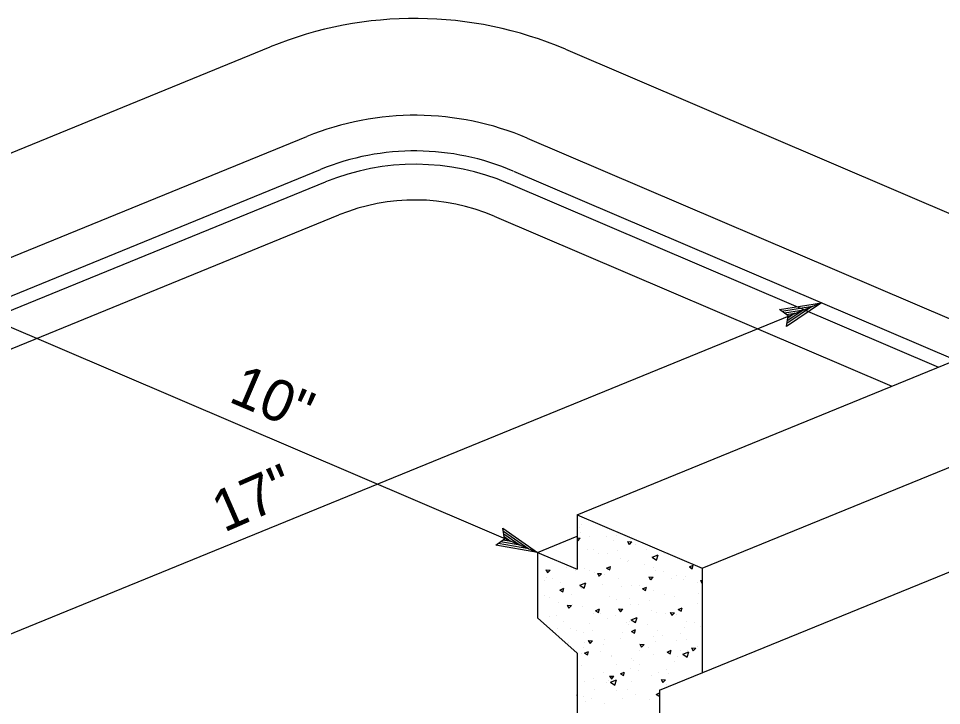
# Model space of a CAD drawing. Extents: x -123486 to -116575, y -107066 to -101122.
# Drawn here: x -117088.2 to -116954.3, y -101409.8 to -101310.1 of the extents above; entities that cross this region are included whole.
import ezdxf

# ---------------------------------------------------------------- set-up
doc = ezdxf.new("R2010")
doc.units = 0
for name, color, linetype in [('G-MARK', 7, 'Continuous'), ('G-TEXT', 7, 'Continuous'), ('Misc CnstDet(22)', 7, 'Continuous')]:
    doc.layers.add(name, color=color, linetype=linetype)

msp = doc.modelspace()

# ---------------------------------------------------------------- linework, layer by layer
at = {"layer": 'G-MARK'}
for p, q in [((-116971.72, -101351.36), (-117114.25, -101409.62)), ((-117094.77, -101352.6), (-117012.91, -101387.59))]:
    msp.add_line(p, q, dxfattribs=at)
at = {"layer": 'G-TEXT'}
for p, q in [((-116977.79, -101352.32), (-116971.72, -101351.36)), ((-116976.55, -101353.27), (-116977.79, -101352.32)), ((-116977.79, -101352.32), (-116977.79, -101352.32)), ((-116977.45, -101352.57), (-116973, -101351.86)), ((-116977.1, -101352.82), (-116974.28, -101352.37)), ((-116971.72, -101351.36), (-116976.8, -101354.8)), ((-116973.01, -101351.87), (-116976.72, -101354.38)), ((-116974.28, -101352.37), (-116976.68, -101354)), ((-116971.72, -101351.36), (-116971.72, -101351.36)), ((-116976.81, -101353.08), (-116975.57, -101352.88)), ((-116976.8, -101354.8), (-116976.55, -101353.27)), ((-116975.57, -101352.88), (-116976.59, -101353.57)), ((-116976.8, -101354.8), (-116976.8, -101354.8)), ((-117017.72, -101385.62), (-117017.95, -101384.07)), ((-117017.95, -101384.07), (-117017.95, -101384.07)), ((-117017.95, -101384.07), (-117012.91, -101387.59)), ((-117017.88, -101384.49), (-117014.18, -101387.07)), ((-117018.96, -101386.54), (-117017.72, -101385.62)), ((-117015.46, -101386.54), (-117018.31, -101386.05)), ((-117016.74, -101386.02), (-117017.96, -101385.8)), ((-117017.8, -101384.91), (-117015.46, -101386.54)), ((-117017.77, -101385.29), (-117016.74, -101386.02)), ((-117012.91, -101387.59), (-117018.96, -101386.54)), ((-117018.96, -101386.54), (-117018.96, -101386.54)), ((-117014.19, -101387.07), (-117018.61, -101386.3)), ((-117012.91, -101387.59), (-117012.91, -101387.59))]:
    msp.add_line(p, q, dxfattribs=at)
at = {"layer": 'Misc CnstDet(22)'}
for p, q in [((-117181.69, -101367.35), (-117051.7, -101314.22)), ((-117008.88, -101314.56), (-116938.85, -101344.49)), ((-117168.96, -101377.33), (-117046.39, -101327.22)), ((-117014.4, -101327.48), (-116952.83, -101353.79)), ((-117168.08, -101382.57), (-117044.43, -101332.02)), ((-117016.43, -101332.24), (-116952.31, -101359.65)), ((-117165.58, -101383.64), (-117043.69, -101333.81)), ((-117017.2, -101334.02), (-116954.75, -101360.71)), ((-117158.88, -101386.5), (-117041.73, -101338.61)), ((-117019.23, -101338.79), (-116961.49, -101363.47)), ((-117007.18, -101382.14), (-116952.87, -101359.94)), ((-116989.02, -101389.9), (-116939.05, -101369.47)), ((-117007.18, -101382.14), (-116989.02, -101389.9)), ((-117007.18, -101382.14), (-117007.18, -101390.04)), ((-116995.2, -101407.6), (-116933.16, -101382.24)), ((-117006.89, -101383.95), (-117006.89, -101383.95)), ((-117006.7, -101384.63), (-117006.7, -101384.63)), ((-117006.49, -101383.54), (-117006.49, -101383.54)), ((-117012.91, -101387.59), (-117007.18, -101385.25)), ((-117007.18, -101385.5), (-117006.71, -101385.53)), ((-117007.18, -101385.75), (-117007.08, -101385.92)), ((-117007.08, -101385.92), (-117006.71, -101385.53)), ((-117005.31, -101385.3), (-117005.31, -101385.3)), ((-117002.85, -101385.24), (-117002.85, -101385.24)), ((-117001.94, -101385.93), (-117001.94, -101385.93)), ((-117001.42, -101385.14), (-117001.42, -101385.14)), ((-116999.85, -101386.01), (-116999.6, -101386.44)), ((-116999.85, -101386.01), (-116999.23, -101386.05)), ((-116999.59, -101386.44), (-116999.23, -101386.06)), ((-116999.42, -101385.77), (-116999.42, -101385.77)), ((-117005.66, -101387.13), (-117005.66, -101387.13)), ((-117004.8, -101387.19), (-117004.8, -101387.19)), ((-117001.36, -101387.35), (-117001.36, -101387.35)), ((-116998.67, -101386.5), (-116998.67, -101386.5)), ((-116997.18, -101387.23), (-116997.18, -101387.23)), ((-117012.91, -101387.59), (-117007.18, -101390.04)), ((-117012.91, -101387.59), (-117012.91, -101397.07)), ((-117004.12, -101387.71), (-117004.12, -101387.71)), ((-117002.79, -101387.82), (-117002.79, -101387.82)), ((-117000.9, -101388.43), (-117000.9, -101388.43)), ((-116996.3, -101388.29), (-116995.43, -101387.95)), ((-116996.3, -101388.29), (-116995.68, -101388.7)), ((-116995.68, -101388.71), (-116995.43, -101387.95)), ((-116994.54, -101387.78), (-116994.54, -101387.78)), ((-116992.43, -101388.52), (-116992.43, -101388.52)), ((-117008.77, -101389.82), (-117008.77, -101389.82)), ((-117006.17, -101389.87), (-117006.17, -101389.87)), ((-117002.89, -101389.88), (-117002.32, -101389.62)), ((-117002.89, -101389.88), (-117002.45, -101390.13)), ((-117002.45, -101390.13), (-117002.32, -101389.62)), ((-116999.93, -101388.98), (-116999.93, -101388.98)), ((-116999.76, -101388.78), (-116999.76, -101388.78)), ((-116997.41, -101389.4), (-116997.41, -101389.4)), ((-116996.15, -101389.73), (-116996.15, -101389.73)), ((-116990.89, -101389.71), (-116990.33, -101389.45)), ((-116990.89, -101389.71), (-116990.46, -101389.96)), ((-116990.46, -101389.97), (-116990.32, -101389.45)), ((-116989.04, -101390.07), (-116989.04, -101390.07)), ((-116989.02, -101389.9), (-116989.02, -101405.08)), ((-117011.73, -101390.11), (-117011.47, -101390.53)), ((-117011.73, -101390.11), (-117011.1, -101390.15)), ((-117011.55, -101391.29), (-117011.55, -101391.29)), ((-117011.47, -101390.54), (-117011.1, -101390.15)), ((-117010.69, -101391.36), (-117010.69, -101391.36)), ((-117007.46, -101390.23), (-117007.46, -101390.23)), ((-117005.38, -101390.18), (-117005.38, -101390.18)), ((-117004.63, -101390.52), (-117004.63, -101390.52)), ((-117004.24, -101390.63), (-117003.99, -101391.06)), ((-117004.24, -101390.63), (-117003.62, -101390.67)), ((-117004.01, -101391.12), (-117004.01, -101391.12)), ((-117003.99, -101391.06), (-117003.62, -101390.68)), ((-117003.13, -101390.83), (-117003.13, -101390.83)), ((-116996.76, -101391.15), (-116996.51, -101391.58)), ((-116996.76, -101391.15), (-116996.14, -101391.2)), ((-116996.5, -101391.58), (-116996.14, -101391.2)), ((-116995.8, -101390.25), (-116995.8, -101390.25)), ((-116994.69, -101390.37), (-116994.69, -101390.37)), ((-116992.69, -101391.01), (-116992.69, -101391.01)), ((-116991.39, -101391.03), (-116991.39, -101391.03)), ((-117011.88, -101391.61), (-117011.88, -101391.61)), ((-117009.55, -101391.93), (-117009.55, -101391.93)), ((-117006.79, -101392.35), (-117005.92, -101392.01)), ((-117006.79, -101392.35), (-117006.17, -101392.77)), ((-117006.65, -101392.66), (-117006.65, -101392.66)), ((-117006.17, -101392.77), (-117005.92, -101392.02)), ((-117003.51, -101392.28), (-117003.51, -101392.28)), ((-117001.19, -101391.45), (-117001.19, -101391.45)), ((-117000.68, -101392.57), (-117000.68, -101392.57)), ((-116999.25, -101392.42), (-116999.25, -101392.42)), ((-116998.07, -101392.43), (-116998.07, -101392.43)), ((-116997.69, -101392.88), (-116997.12, -101392.62)), ((-116997.26, -101393.13), (-116997.12, -101392.62)), ((-116997.07, -101392.72), (-116997.07, -101392.72)), ((-116993.46, -101391.45), (-116993.46, -101391.45)), ((-116991.76, -101391.55), (-116991.76, -101391.55)), ((-116989.65, -101391.96), (-116989.65, -101391.96)), ((-116989.28, -101391.68), (-116989.02, -101392.1)), ((-116989.28, -101391.68), (-116989.02, -101391.69)), ((-116989.02, -101392.11), (-116989.02, -101392.11)), ((-117011.95, -101393.83), (-117011.95, -101393.83)), ((-117009.68, -101393.05), (-117009.12, -101392.79)), ((-117009.68, -101393.05), (-117009.25, -101393.3)), ((-117009.25, -101393.3), (-117009.12, -101392.79)), ((-117007.92, -101393.66), (-117007.92, -101393.66)), ((-117006.51, -101392.88), (-117006.51, -101392.88)), ((-117002.46, -101393.92), (-117002.46, -101393.92)), ((-116997.69, -101392.88), (-116997.26, -101393.13)), ((-116996.06, -101393.06), (-116996.06, -101393.06)), ((-116994.49, -101393.72), (-116994.49, -101393.72)), ((-116993.03, -101394.02), (-116993.03, -101394.02)), ((-116993.03, -101394.02), (-116993.03, -101394.02)), ((-116989.5, -101393.5), (-116989.5, -101393.5)), ((-117011.18, -101394.18), (-117011.18, -101394.18)), ((-117009.89, -101394.93), (-117009.89, -101394.93)), ((-117008.64, -101395.25), (-117008.38, -101395.68)), ((-117008.64, -101395.25), (-117008.01, -101395.29)), ((-117008.38, -101395.68), (-117008.01, -101395.3)), ((-117007.91, -101395.13), (-117007.91, -101395.13)), ((-117001.45, -101394.48), (-117001.45, -101394.48)), ((-116999.56, -101394.33), (-116999.56, -101394.33)), ((-116999.44, -101395.11), (-116999.44, -101395.11)), ((-116998.33, -101395.19), (-116998.33, -101395.19)), ((-116996.73, -101394.62), (-116996.73, -101394.62)), ((-116989.74, -101395.01), (-116989.74, -101395.01)), ((-117010.14, -101396.69), (-117010.14, -101396.69)), ((-117006.42, -101395.48), (-117006.42, -101395.48)), ((-117004.82, -101396.53), (-117004.82, -101396.53)), ((-117004.49, -101396.05), (-117003.92, -101395.79)), ((-117004.49, -101396.05), (-117004.05, -101396.3)), ((-117004.05, -101396.3), (-117003.92, -101395.79)), ((-117003.97, -101395.71), (-117003.97, -101395.71)), ((-117003.72, -101396.39), (-117003.72, -101396.39)), ((-117001.66, -101396.78), (-117001.66, -101396.78)), ((-117001.15, -101395.77), (-117000.9, -101396.2)), ((-117001.15, -101395.77), (-117000.53, -101395.82)), ((-117000.9, -101396.2), (-117000.53, -101395.82)), ((-116996.4, -101396.07), (-116996.4, -101396.07)), ((-116995.61, -101396.38), (-116995.61, -101396.38)), ((-116994.29, -101396.49), (-116994.29, -101396.49)), ((-116993.67, -101396.3), (-116993.41, -101396.72)), ((-116993.67, -101396.3), (-116993.05, -101396.34)), ((-116993.41, -101396.73), (-116993.05, -101396.34)), ((-116992.77, -101396.67), (-116992.77, -101396.67)), ((-116992.49, -101395.88), (-116991.93, -101395.62)), ((-116992.49, -101395.88), (-116992.06, -101396.13)), ((-116992.06, -101396.13), (-116991.93, -101395.62)), ((-117007.18, -101402.21), (-117012.91, -101397.07)), ((-117011.19, -101396.83), (-117011.19, -101396.83)), ((-117009.17, -101397.6), (-117009.17, -101397.6)), ((-117005.39, -101397.98), (-117005.39, -101397.98)), ((-117002.82, -101397.16), (-117002.82, -101397.16)), ((-117000.02, -101397.76), (-117000.02, -101397.76)), ((-116999.78, -101398.12), (-116999.78, -101398.12)), ((-116999.6, -101397.67), (-116999.6, -101397.67)), ((-116999.31, -101397.36), (-116998.44, -101397.02)), ((-116999.31, -101397.36), (-116998.69, -101397.78)), ((-116998.69, -101397.78), (-116998.44, -101397.02)), ((-116996.91, -101398.08), (-116996.91, -101398.08)), ((-116991.34, -101397.66), (-116991.34, -101397.66)), ((-116990.11, -101397.75), (-116990.11, -101397.75)), ((-117010.77, -101398.98), (-117010.72, -101398.96)), ((-117010.73, -101399.02), (-117010.72, -101398.96)), ((-117010.07, -101398.59), (-117010.07, -101398.59)), ((-117008.2, -101398.58), (-117008.2, -101398.58)), ((-117007.24, -101398.88), (-117007.24, -101398.88)), ((-117006.19, -101399.22), (-117006.19, -101399.22)), ((-117004.99, -101398.86), (-117004.99, -101398.86)), ((-117000.63, -101399.28), (-117000.63, -101399.28)), ((-116999.29, -101399.05), (-116998.72, -101398.79)), ((-116999.29, -101399.05), (-116998.86, -101399.3)), ((-116998.86, -101399.3), (-116998.72, -101398.79)), ((-116995.56, -101398.96), (-116995.56, -101398.96)), ((-116992.15, -101399.38), (-116992.15, -101399.38)), ((-116991.65, -101398.43), (-116991.65, -101398.43)), ((-116989.33, -101398.3), (-116989.33, -101398.3)), ((-117008.49, -101400.67), (-117008.49, -101400.67)), ((-117006.12, -101400.64), (-117006.12, -101400.64)), ((-117005.55, -101400.39), (-117005.29, -101400.82)), ((-117005.55, -101400.39), (-117004.92, -101400.44)), ((-117005.29, -101400.82), (-117004.92, -101400.44)), ((-117003.16, -101400.17), (-117003.16, -101400.17)), ((-117000.86, -101400.14), (-117000.86, -101400.14)), ((-116996.07, -101399.81), (-116996.07, -101399.81)), ((-116995.87, -101400.58), (-116995.87, -101400.58)), ((-116994.72, -101399.72), (-116994.72, -101399.72)), ((-116992.71, -101400.35), (-116992.71, -101400.35)), ((-116991.37, -101400.22), (-116991.37, -101400.22)), ((-117006.25, -101401.33), (-117006.25, -101401.33)), ((-117006.09, -101402.22), (-117005.52, -101401.96)), ((-117005.65, -101402.47), (-117005.52, -101401.96)), ((-117003.73, -101401.97), (-117003.73, -101401.97)), ((-117003.29, -101400.94), (-117003.29, -101400.94)), ((-116998.09, -101401.77), (-116998.09, -101401.77)), ((-116998.06, -101400.92), (-116997.81, -101401.34)), ((-116998.06, -101400.92), (-116997.44, -101400.96)), ((-116997.81, -101401.35), (-116997.44, -101400.96)), ((-116996.82, -101401.43), (-116996.82, -101401.43)), ((-116994.09, -101402.05), (-116993.53, -101401.79)), ((-116994.09, -101402.05), (-116993.66, -101402.3)), ((-116993.66, -101402.3), (-116993.53, -101401.79)), ((-116992.11, -101401.86), (-116992.11, -101401.86)), ((-116991.84, -101402.37), (-116990.96, -101402.03)), ((-116991.21, -101402.79), (-116990.96, -101402.03)), ((-116991.11, -101401.88), (-116991.11, -101401.88)), ((-116990.58, -101401.44), (-116990.32, -101401.87)), ((-116990.58, -101401.44), (-116989.96, -101401.48)), ((-116990.32, -101401.87), (-116989.96, -101401.48)), ((-116989.67, -101401.31), (-116989.67, -101401.31)), ((-117007.18, -101402.21), (-117007.18, -101469.41)), ((-117006.53, -101402.23), (-117006.53, -101402.23)), ((-117006.09, -101402.22), (-117005.65, -101402.47)), ((-117002.17, -101402.69), (-117002.17, -101402.69)), ((-117002.13, -101402.61), (-117002.13, -101402.61)), ((-116999.34, -101402.99), (-116999.34, -101402.99)), ((-116998.98, -101403.27), (-116998.98, -101403.27)), ((-116996.09, -101402.4), (-116996.09, -101402.4)), ((-116993.05, -101403.36), (-116993.05, -101403.36)), ((-116992.63, -101402.7), (-116992.63, -101402.7)), ((-116991.84, -101402.37), (-116991.21, -101402.79)), ((-117006.58, -101404.07), (-117006.58, -101404.07)), ((-117001.47, -101403.82), (-117001.47, -101403.82)), ((-116999.46, -101404.45), (-116999.46, -101404.45)), ((-116998.22, -101404.74), (-116998.22, -101404.74)), ((-116998.09, -101403.9), (-116998.09, -101403.9)), ((-116994.22, -101404.57), (-116994.22, -101404.57)), ((-117004.84, -101405.87), (-117004.84, -101405.87)), ((-117003.39, -101405.08), (-117003.39, -101405.08)), ((-117002.63, -101406.12), (-117002.63, -101406.12)), ((-117002.46, -101405.54), (-117002.2, -101405.96)), ((-117002.46, -101405.54), (-117001.83, -101405.58)), ((-117002.33, -101406.43), (-117001.45, -101406.1)), ((-117002.2, -101405.97), (-117001.83, -101405.58)), ((-117001.7, -101406.85), (-117001.45, -101406.1)), ((-117000.89, -101405.22), (-117000.33, -101404.96)), ((-117000.89, -101405.22), (-117000.46, -101405.47)), ((-117000.46, -101405.47), (-117000.32, -101404.96)), ((-116996.43, -101405.41), (-116996.43, -101405.41)), ((-116995.38, -101405.04), (-116995.38, -101405.04)), ((-116994.97, -101406.06), (-116994.72, -101406.49)), ((-116994.97, -101406.06), (-116994.35, -101406.1)), ((-116994.72, -101406.49), (-116994.35, -101406.1)), ((-116993.9, -101405.17), (-116993.9, -101405.17)), ((-117006.15, -101406.33), (-117006.15, -101406.33)), ((-117002.84, -101406.51), (-117002.84, -101406.51)), ((-117002.33, -101406.43), (-117001.7, -101406.85)), ((-116999.8, -101407.46), (-116999.8, -101407.46)), ((-116999.35, -101406.38), (-116999.35, -101406.38)), ((-116994.26, -101406.79), (-116994.26, -101406.79)), ((-117007.18, -101408.34), (-117007.12, -101408.13)), ((-117007.18, -101408.15), (-117007.12, -101408.13)), ((-117006.21, -101408.56), (-117006.21, -101408.56)), ((-117005.11, -101408.84), (-117005.11, -101408.84)), ((-117004.65, -101407.55), (-117004.65, -101407.55)), ((-117001.39, -101407.63), (-117001.39, -101407.63)), ((-117000.61, -101408.85), (-117000.61, -101408.85)), ((-116998.68, -101408.17), (-116998.68, -101408.17)), ((-116995.7, -101408.22), (-116995.2, -101407.99)), ((-116995.7, -101408.22), (-116995.26, -101408.47)), ((-116995.26, -101408.47), (-116995.2, -101408.23)), ((-116995.2, -101407.6), (-116995.2, -101474.53)), ((-117005.9, -101409.3), (-117005.9, -101409.3)), ((-117003.18, -101409.52), (-117003.18, -101409.52)), ((-116996.63, -101408.93), (-116996.63, -101408.93))]:
    msp.add_line(p, q, dxfattribs=at)
for radius in [55.52, 41.47, 36.29, 34.35, 29.17]:
    msp.add_arc((-117030.7, -101365.61), radius, 66.8572, 112.2327, dxfattribs=at)

# ---------------------------------------------------------------- texts
for s, rotation, p in [('10"', 336.8572, (-117057.92, -101365.64)), ('17"', 23.6156, (-117058.42, -101384.75))]:
    msp.add_text(s, height=6, rotation=rotation, dxfattribs=at).set_placement(p)

doc.saveas('drawing.dxf')
